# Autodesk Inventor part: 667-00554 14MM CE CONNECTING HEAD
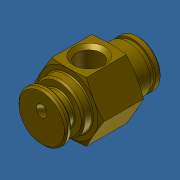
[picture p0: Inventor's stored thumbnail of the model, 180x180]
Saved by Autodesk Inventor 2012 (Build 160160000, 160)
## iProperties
Created: 2013-10
Part Number: 667-00554 14MM CE CONNECTING HEAD
Material: BRASS 340
Document SubType Name: Modeling
Designer: Admin
Density: 8.47 g/cm^3
Mass: 37.1676 g
Surface Area: 22.9823 cm^2
Volume: 4.38815 cm^3
Author: Admin
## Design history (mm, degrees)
node "667-00554 14MM CE CONNECTING HEAD1"
node "Base1"
body "Solid1"
